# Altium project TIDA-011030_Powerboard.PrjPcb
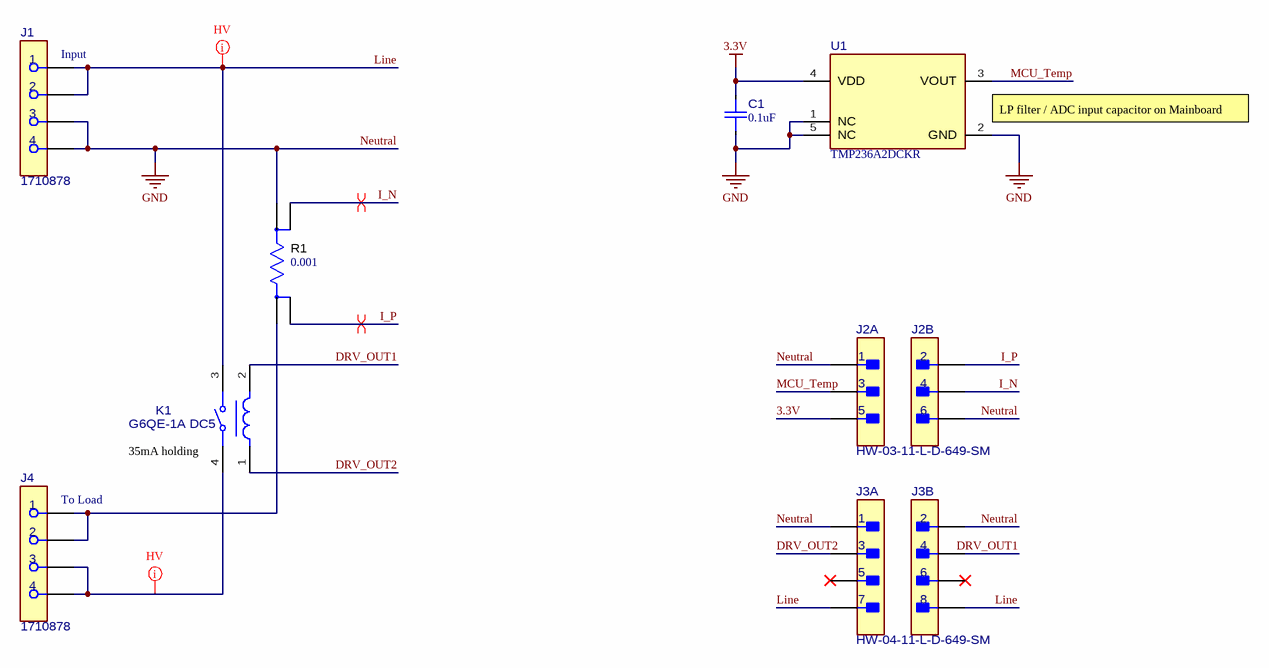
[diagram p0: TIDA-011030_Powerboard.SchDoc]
CopyrightYear: 2026; PCB_Layout: Simon Bozowicki; PCB_Rev: E1; PRJ_Customer: Public Release; PRJ_Engineer: Simon Bozowicki; PRJ_Number: TIDA-011030; PRJ_Title: Smart Circuit Breaker; SCH_Rev: E1; TechSupport: http://www.ti.com/support; TID: TIDA-011030
2 sheets, 20 parts. Net scope: global (net labels, ports and power ports of the same name join across sheets).
Board file: TIDA-011030_Powerboard.PcbDoc
Sheets:
  TIDA-011030_Powerboard.SchDoc
  TIDA-011030_Powerboard_Hardware.SchDoc

## Sheet TIDA-011030_Powerboard.SchDoc: Powerboard
size 431 x 279 mm; Date: Not shown in title block; ApprovedBy: Not shown in title block; CheckedBy: Not shown in title block; Author: Not shown in title block; CompanyName: Not shown in title block; Engineer: Not shown in title block; Organization: Not shown in title block; Address1: Not shown in title block; Address2: Not shown in title block; Address3: Not shown in title block; Address4: Not shown in title block; DocumentNumber: 2; Revision: Use project parameter SCH_Rev; SheetNumber: 1; SheetTotal: 2; PageSetup: Record=PageOptions¦CenterHorizontal=True¦CenterVertical=True¦PrintScale=1.00¦XCorrection=1.00¦YCorrection=1.00¦PrintKind=0¦BorderSize=5000000¦LeftOffset=0¦BottomOffset=0¦Orientation=2¦PaperLength=1000¦PaperWidth=1000¦Scale=100¦PaperSource=15¦PrintQuality=600¦MediaType=1¦DitherType=10¦PaperKind=Letter¦PrintScaleMode=1

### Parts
C1  ValueDisplayed: 0.1uF  [FP-GRM155R71H104KE14D_0402-MFG]  (hidden comment: GRM155R71H104KE14D)
J1  1710878  [FP-1710878_TERM_BLK_4-MFG]
J2  HW-03-11-L-D-649-SM  [FP-HW-03-11-L-D-649-SM_HDR8-MFG]  (parts A,B of 2)
J3  HW-04-11-L-D-649-SM  [FP-HW-04-11-L-D-649-SM_HDR8-MFG]  (parts A,B of 2)
J4  1710878  [FP-1710878_TERM_BLK_4-MFG]
K1  G6QE-1A DC5  [FP-G6QE-1A DC5_PTH_RELAY_30MM5_16MM0-MFG]
R1  value 0.001  [FP-WSK12161L000FEA_1216-MFG]  (hidden comment: WSK12161L000FEA)
U1  TMP236A2DCKR  [DCK0005A-MFG]

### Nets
3.3V: C1.2 J2.5 U1.4(VDD)
Neutral: C1.1 J1.3 J1.4 J2.1 J2.6 J3.1 J3.2 R1.3 U1.1(NC) U1.2(GND) U1.5(NC)  [also labelled GND]
DRV_OUT1: J3.4 K1.2
DRV_OUT2: J3.3 K1.1
I_N: J2.4 R1.1
I_P: J2.2 R1.2
Line: J1.1 J1.2 J3.7 J3.8 K1.3
MCU_Temp: J2.3 U1.3(VOUT)
NetJ4_1: J4.1 J4.2 R1.4
NetJ4_3: J4.3 J4.4 K1.4

Not connected (* = marked no-connect by the designer): J3 5* 6*

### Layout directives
differential pair; net class LV: I_N, I_P
net class HV: Line, NetJ4_3

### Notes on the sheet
- (near J1) Input
- (near U1) LP filter / ADC input capacitor on Mainboard
- (near J4) To Load
- (near K1) 35mA holding

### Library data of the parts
C1 = CMP-0096855-1: Chip Multilayer Ceramic Capacitors for General Purpose, 0402, 0.10uF, X7R, 15%, 10%, 50V; Manufacturer: Murata; SizeZ_mm: 0.55mm; Value: 100nF; AEC Qualified: No
J1 J4 = CMP-0128751-1: Conn PC Terminal Block F 4 POS 5mm Solder ST Thru-Hole 24A; Manufacturer: Phoenix Contact; ContactFinish: Tin; Row_Count: 1; Voltage_V: 400V; AEC Qualified: No; Conn Gender: Female; Conn Orientation: Horizontal; Is Female: yes; Max Wire Gauge: 12; Min Wire Gauge: 24; SizeZ_mm: 18.2mm; TaMax_C: +105°C; TaMin_C: -40°C
J2 = CMP-0128773-1: High Temperature Flexible Board Stacking Header for Surface Mount, 0.100" Pitch 6 pins 2 rows; Manufacturer: Samtec; ContactFinish: Gold,Nickel; Row_Count: 2; AEC Qualified: No; Conn Gender: Male; Conn Orientation: Straight; DUT-Pitch_mm: 2.54mm; SizeZ_mm: 22.1mm; System: Connector
J3 = CMP-0128774-1: High Temperature Flexible Board Stacking Header for Surface Mount, 0.100" Pitch 8 pins 2 rows; Manufacturer: Samtec; ContactFinish: Gold,Nickel; Row_Count: 2; AEC Qualified: No; Conn Gender: Male; Conn Orientation: Straight; DUT-Pitch_mm: 2.54mm; SizeZ_mm: 22.1mm; System: Connector
K1 = CMP-0049581-1: General Purpose Relay SPST-NO (1 Form A) 5VDC Coil Through Hole 32A; Manufacturer: Omron; Coil Current_A: 280mA; Coil Power_W: 1.4W; Coil Type: Non-Latching; Coil Voltage_VDC: 5V; Contact Rating_A: 36A; SizeZ_mm: 20.5mm; AEC Qualified: No; Coil Resistance: 17.9Ω; TaMax_C: +60°C; TaMin_C: -40°C
R1 = CMP-0097727-1: Res Metal Strip 1216 0.001 Ohm 1% 3W ±150ppm/C Pad SMD T/R; Manufacturer: Vishay Dale; AEC Grade: Grade 0; Res_ohm: 1m; TempCo: 50ppm/°C; AEC Qualified: Yes; SizeZ_mm: 1.9mm
U1 = CMP-0124009-1: Low-Power, High-Accuracy Analog Output Temperature Sensors; Manufacturer: Texas Instruments; SizeZ_mm: 1.1mm; AEC Qualified: No; Max Supply Voltage: 5.5V; Min Supply Voltage: 3.1V; Operating Supply Current: 10uA; Sensor Output: Analog Voltage; Standoff Height: 0mm; TaMax_C: +150°C; TaMin_C: -40°C

## Sheet TIDA-011030_Powerboard_Hardware.SchDoc: Hardware
size 431 x 279 mm; Date: Not shown in title block; ApprovedBy: Not shown in title block; CheckedBy: Not shown in title block; Author: Not shown in title block; CompanyName: Not shown in title block; Engineer: Not shown in title block; Organization: Not shown in title block; Address1: Not shown in title block; Address2: Not shown in title block; Address3: Not shown in title block; Address4: Not shown in title block; DocumentNumber: 3; Revision: Use project parameter SCH_Rev; SheetNumber: 2; SheetTotal: 2; PageSetup: Record=PageOptions¦CenterHorizontal=True¦CenterVertical=True¦PrintScale=1.00¦XCorrection=1.00¦YCorrection=1.00¦PrintKind=0¦BorderSize=5000000¦LeftOffset=0¦BottomOffset=0¦Orientation=2¦PaperLength=1000¦PaperWidth=1000¦Scale=100¦PaperSource=15¦PrintQuality=600¦MediaType=1¦DitherType=10¦PaperKind=Letter¦PrintScaleMode=1
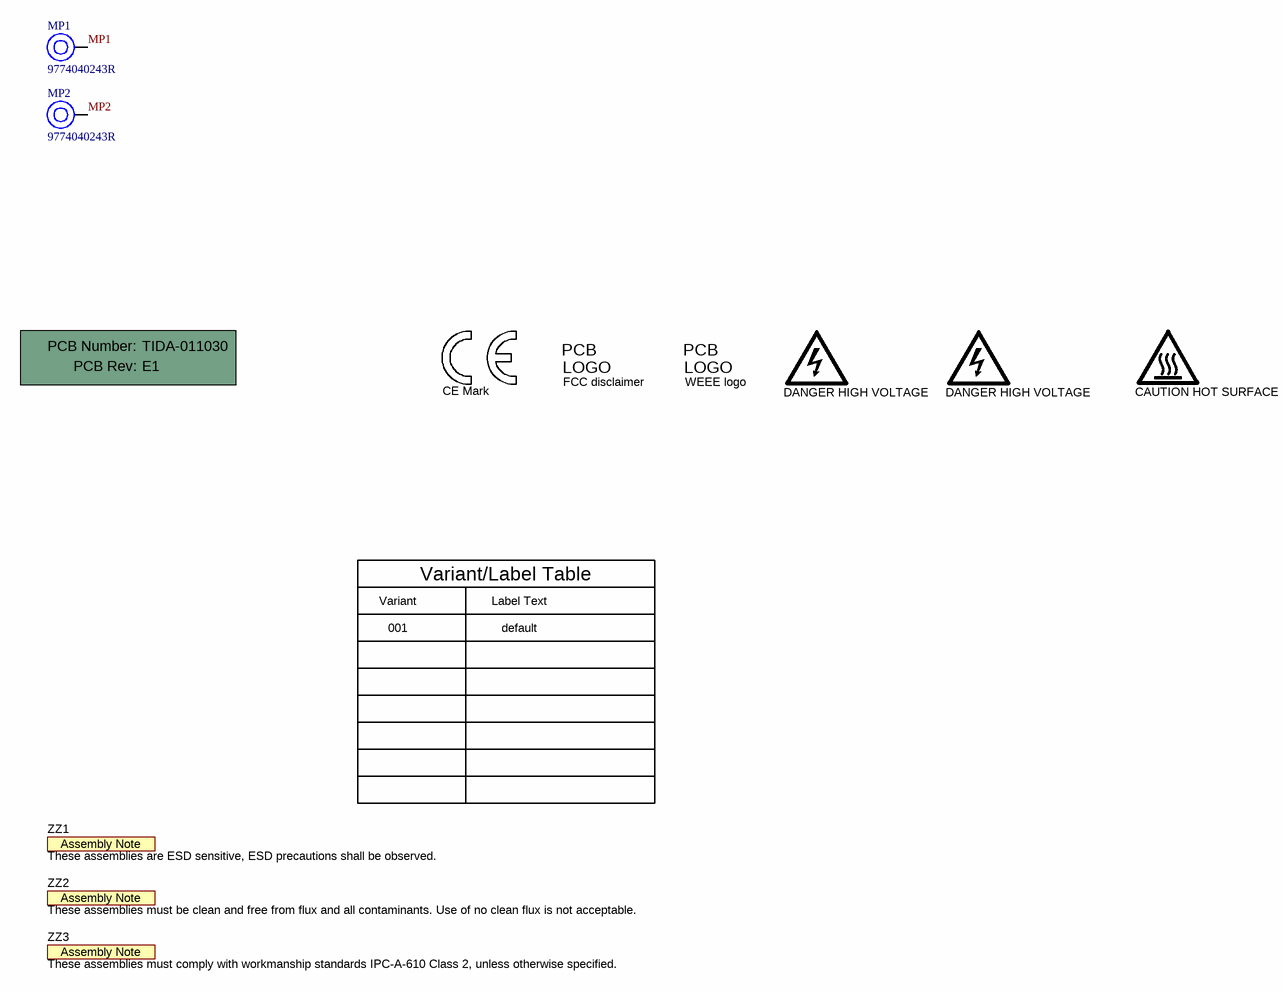
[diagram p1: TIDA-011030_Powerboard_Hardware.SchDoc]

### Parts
!PCB1  Printed Circuit Board  (value not drawn)  (mechanical)
Logo1  CE Mark  [CE_Mark_5mm]  (no BOM)
Logo3  FCC disclaimer  [FCC_disclaimer]  (no BOM)
Logo4  WEEE logo  [WEEE_Minimum]  (no BOM)
LOGO5  DANGER HIGH VOLTAGE  [IEC_HighVoltage_Small]  (no BOM)
LOGO6  DANGER HIGH VOLTAGE  [IEC_HighVoltage_Small]  (no BOM)
Logo7  CAUTION HOT SURFACE  [IEC_HotSurface_Small]  (no BOM)
MP1  9774040243R  [9774040243]
MP2  9774040243R  [9774040243]
ZZ1  These assemblies are ESD sensitive, ESD precautions shall be observed.  [AssemblyNote]  (no BOM)
ZZ2  These assemblies must be clean and free from flux and all contaminants. Use of no clean flux is not acceptable.  [AssemblyNote]  (no BOM)
ZZ3  These assemblies must comply with workmanship standards IPC-A-610 Class 2, unless otherwise specified.  [AssemblyNote]  (no BOM)

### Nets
MP1: MP1.1
MP2: MP2.1

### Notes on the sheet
- Variant
- Variant/Label Table
- Label Text
- 001
- default

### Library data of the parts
!PCB1 = CMP-0003618-2: Manufacturer: Any; PartNumber: TIDA-011030
Logo1 = CMP-0074844-1: SymbolCreator: a0412235
Logo3 = CMP-0074847-1: FCC_disclaimer; Library Reference: Logo
Logo4 = CMP-0074769-1
LOGO5 LOGO6 = CMP-0074835-1: IEC 61010-1 High Voltage Warning; SymbolCreator: a0412235; Lib Reference: IEC_HighVoltage
Logo7 = CMP-0074837-2: IEC 61010-1 Hot Surface Warning; Manufacturer: Texas Instruments; CompType: IC; AEC Category: Q200; SymbolCreator: a0412235
MP1 MP2 = CMP-03913-59774868-2: Spacer, Steel, With Internal Thread M2, 4MM Length, 4.35MM Outer Diameter; Threaded/Unthreaded: Threaded; Outside Diameter: 4.3434mm; Plating: Tin
ZZ1 = CMP-0077236-1
ZZ2 = CMP-0077237-1
ZZ3 = CMP-0077238-1

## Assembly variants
001: all parts fitted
